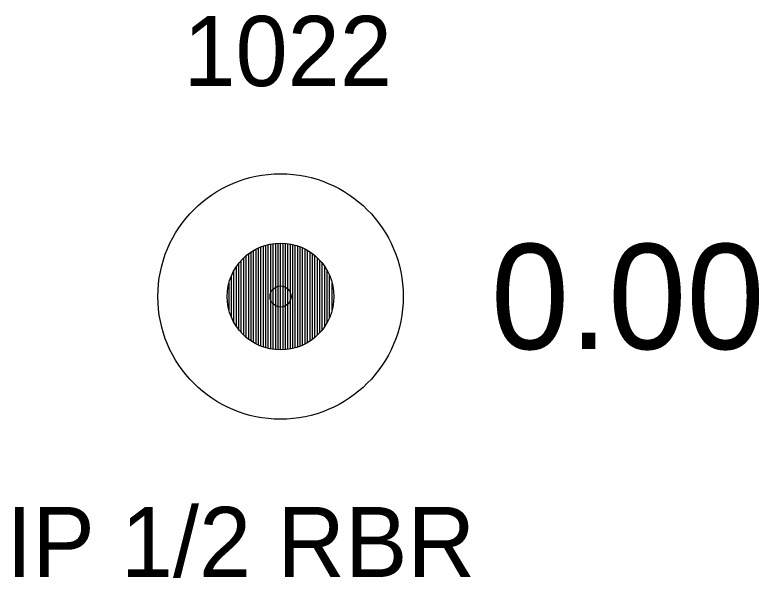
# Model space of a CAD drawing. Extents: x 1448136 to 1453623, y 1125056 to 1128842.
# Drawn here: x 1448499.51 to 1448510.13, y 1126368.24 to 1126376.27 of the extents above; entities that cross this region are included whole.
import ezdxf

# ---------------------------------------------------------------- set-up
doc = ezdxf.new("R2010")
doc.units = 0
for name, color, linetype in [('RD_EX_DV_Prop_txCode', 7, 'Continuous'), ('RD_EX_DV_PropPin', 7, 'Continuous'), ('RD_EX_TX_DV_Prop_ELEV', 7, 'Continuous'), ('RD_SMD_Locator', 7, 'Continuous')]:
    doc.layers.add(name, color=color, linetype=linetype)

msp = doc.modelspace()

# ---------------------------------------------------------------- linework, layer by layer
at = {"layer": 'RD_EX_DV_PropPin'}
for p, q in [((1448503.231, 1126371.498), (1448503.231, 1126373.013)), ((1448503.266, 1126371.495), (1448503.266, 1126373.016)), ((1448503.301, 1126371.495), (1448503.301, 1126373.017)), ((1448503.336, 1126371.495), (1448503.336, 1126373.016)), ((1448503.371, 1126371.498), (1448503.371, 1126373.013)), ((1448502.916, 1126371.599), (1448502.916, 1126372.912)), ((1448502.951, 1126371.58), (1448502.951, 1126372.931)), ((1448502.986, 1126371.563), (1448502.986, 1126372.948)), ((1448503.021, 1126371.548), (1448503.021, 1126372.963)), ((1448503.056, 1126371.535), (1448503.056, 1126372.976)), ((1448503.091, 1126371.524), (1448503.091, 1126372.987)), ((1448503.126, 1126371.515), (1448503.126, 1126372.996)), ((1448503.161, 1126371.508), (1448503.161, 1126373.004)), ((1448503.196, 1126371.502), (1448503.196, 1126373.009)), ((1448503.406, 1126371.502), (1448503.406, 1126373.009)), ((1448503.441, 1126371.508), (1448503.441, 1126373.004)), ((1448503.476, 1126371.515), (1448503.476, 1126372.996)), ((1448503.511, 1126371.524), (1448503.511, 1126372.987)), ((1448503.546, 1126371.535), (1448503.546, 1126372.976)), ((1448503.581, 1126371.548), (1448503.581, 1126372.963)), ((1448503.616, 1126371.563), (1448503.616, 1126372.948)), ((1448503.651, 1126371.58), (1448503.651, 1126372.931)), ((1448503.686, 1126371.599), (1448503.686, 1126372.912)), ((1448502.776, 1126371.705), (1448502.776, 1126372.806)), ((1448502.811, 1126371.673), (1448502.811, 1126372.838)), ((1448502.846, 1126371.646), (1448502.846, 1126372.865)), ((1448502.881, 1126371.621), (1448502.881, 1126372.89)), ((1448503.721, 1126371.621), (1448503.721, 1126372.89)), ((1448503.756, 1126371.646), (1448503.756, 1126372.865)), ((1448503.791, 1126371.673), (1448503.791, 1126372.838)), ((1448503.826, 1126371.705), (1448503.826, 1126372.806)), ((1448502.706, 1126371.781), (1448502.706, 1126372.73)), ((1448502.741, 1126371.741), (1448502.741, 1126372.771)), ((1448503.861, 1126371.741), (1448503.861, 1126372.771)), ((1448503.896, 1126371.781), (1448503.896, 1126372.73)), ((1448502.636, 1126371.886), (1448502.636, 1126372.625)), ((1448502.671, 1126371.829), (1448502.671, 1126372.682)), ((1448503.931, 1126371.829), (1448503.931, 1126372.682)), ((1448503.966, 1126371.886), (1448503.966, 1126372.625)), ((1448502.601, 1126371.958), (1448502.601, 1126372.554)), ((1448504.001, 1126371.958), (1448504.001, 1126372.554)), ((1448502.566, 1126372.059), (1448502.566, 1126372.452)), ((1448504.036, 1126372.059), (1448504.036, 1126372.452))]:
    msp.add_line(p, q, dxfattribs=at)
for radius in [1.75, 0.761]:
    msp.add_circle((1448503.301, 1126372.256), radius, dxfattribs=at)
at = {"layer": 'RD_SMD_Locator'}
msp.add_circle((1448503.301, 1126372.256), 0.15, dxfattribs=at)

# ---------------------------------------------------------------- texts
at = {"layer": 'RD_EX_DV_Prop_txCode'}
for s, p in [('1022', (1448501.915, 1126375.256)), ('IP 1/2 RBR', (1448499.388, 1126368.256))]:
    msp.add_text(s, height=1, dxfattribs=at).set_placement(p)
at = {"layer": 'RD_EX_TX_DV_Prop_ELEV'}
msp.add_text('0.00', height=1.5, dxfattribs=at).set_placement((1448506.301, 1126371.506))

doc.saveas('drawing.dxf')
